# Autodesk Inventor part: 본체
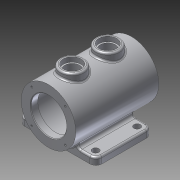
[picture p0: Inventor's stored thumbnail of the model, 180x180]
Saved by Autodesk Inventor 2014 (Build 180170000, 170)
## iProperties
Created: 2014-12
Part Number: 본체
Material: 알루미늄 6061
Document SubType Name: Modeling
Designer: Owner
Density: 2.71 g/cm^3
Appearance: 알루미늄 - 평지
Mass: 1293.91 g
Surface Area: 1040.15 cm^2
Volume: 477.456 cm^3
Author: Owner
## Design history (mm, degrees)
sketch "스케치1"
  geometry: C1 r 46 at (0, 0); 1 further point
  constraints: 1 centre point, 1 coincident
  dimensions: "d0" = 92 diameter of C1
extrude "돌출1" new body sketch "스케치1" stored distance "d1" = 140; taper "d2" = 0 deg
sketch "스케치2"
  geometry: C1 r 46 at (0, 0) reference; C2 r 30 at (0, 0)
  constraints: 1 centre point, 1 coincident
  dimensions: "d3" = 60 diameter of C2
extrude "돌출2" cut sketch "스케치2" stored distance "d4" = 0; taper "d5" = 0 deg
node "작업 평면1"
sketch "스케치3" dims "d28" = 40
  geometry: C1 r 37.5 at (0, 0); 1 further point
  constraints: 1 centre point, 1 coincident
  dimensions: "d7" = 75 diameter of C1
extrude "돌출3" cut sketch "스케치3" distance "d8" = 116; taper "d9" = 0 deg
node "작업 평면2"
sketch "스케치5"
  geometry: L1 (65, 40)-(-65, 40); L2 (-65, 40)-(-65, -55); L3 (-65, -55)-(65, -55); L4 (65, -55)-(65, 40); L5 (-46, -70)-(46, -70) reference; L6 (46, 70)-(-46, 70) reference; 2 further points
  constraints: 8 end point, 2 parallel, 1 horizontal, 1 midpoint, 1 perpendicular, 1 vertical alignment
  dimensions: "d13" = 130 distance of L3.end L2.end; "d14" = 95 distance of L2.end L1.end; "d15" = 15 distance between parallel lines of L5 L3
extrude "돌출4" join sketch "스케치5" distance "d16" = 12; taper "d17" = 0 deg
node "작업 평면3"
sketch "스케치7"
  geometry: L1 (-130, 6)-(-90.923, 6) reference; L2 (-130, -6)-(-130, 6) reference; L3 (-130, -6)-(0, -6) reference; L4 (0, -6)-(0, 6) reference; L5 (-39.077, 6)-(0, 6) reference; L6 (-39.077, 6)-(0, 6) reference; L7 (-130, 6)-(-90.923, 6) reference; C1 r 30 at (-65, 44) reference; C2 r 46 at (-65, 44) reference; A1 r 46 centre (-65, 44) between (-90.923, 6) and (-39.077, 6) reference; A2 r 5 centre (-26.116, 11) between (-29.928, 14.235) and (-26.116, 6); A3 r 5 centre (-103.884, 11) between (-103.884, 6) and (-100.072, 14.235); A4 r 46 centre (-65, 44) between (-39.077, 6) and (-90.923, 6) reference; 1 further point
  constraints: 6 point on circle, 4 tangent, 2 centre point, 2 point on line
  dimensions: "d18" = 10 diameter of A2; "d19" = 10 diameter of A3
extrude "돌출5" join sketch "스케치7" distance "d20" = 95; taper "d21" = 0 deg
node "작업 평면5"
sketch "스케치9"
  geometry: L1 (46, 70)-(-46, 70) reference; C1 r 20 at (0, 30); C2 r 20 at (0, -30); 1 further point
  constraints: 2 centre point, 2 vertical alignment
  dimensions: "d27" = 40 diameter of C1; "d28" = 40 diameter of C2; "d29" = 40 distance from line of C1.centre L1; "d30" = 60 distance of C2.centre C1.centre
extrude "돌출6" join sketch "스케치9" stored distance "d31" = 95; taper "d32" = 0 deg
sketch "스케치10"
  geometry: C1 r 20 at (0, 0) reference; 1 further point
sketch "스케치11"
  geometry: C1 r 20 at (0, 0) reference; 1 further point
hole "구멍1" sketch "스케치10" diameter "d33" = 25; stored, may be unused: countersink angle "d37" = 90 deg, drill point angle "d39" = 118 deg; dims "d34" = 6, "d35" = 30, "d36" = 8, "d38" = 8
hole "구멍2" sketch "스케치11" diameter "d40" = 25; stored, may be unused: countersink angle "d44" = 90 deg, drill point angle "d46" = 118 deg; dims "d41" = 6, "d42" = 30, "d43" = 8, "d45" = 8
sketch "스케치12"
  geometry: L1 (-38.884, 40)-(-65, 40) reference; L2 (-65, 40)-(-65, -55) reference; L3 (-65, -55)-(-38.884, -55) reference; C1 r 5.5 at (-52, 27.5); C2 r 5.5 at (-52, -42.5); 2 further points
  constraints: 2 centre point, 1 other
  dimensions: "d47" = 11 diameter of C1; "d48" = 11 diameter of C2; "d49" = 12.5 distance from line of C1.centre L1; "d50" = 12.5 distance from line of C2.centre L3; "d51" = 13 distance from line of C2.centre L2; "d52" = 13 distance from line of C1.centre L2
extrude "돌출7" cut sketch "스케치12" stored distance "d53" = 95; taper "d54" = 0 deg
sketch "스케치13"
  geometry: L1 (-65, 40)-(-65, -55) reference; C1 r 5.5 at (-52, 27.5) reference; 2 further points
  constraints: 1 other
  dimensions: "d55" = 8 distance from line of point (-57, -7.5) L1; "d56" = 35 vertical distance of point (-57, -7.5) C1.centre
feature "엠보싱1" sketch "스케치13" dims "d57" = 1, "d58" = 0
sketch "스케치14"
  geometry: L1 (0, 0)-(28.284, 28.284); L2 (0, 0)-(40, 0); L3 (0, 0)-(-28.284, 28.284); L4 (0, 0)-(-28.284, -28.284); L5 (0, 0)-(28.284, -28.284); C1 r 30 at (0, 0) reference; C2 r 46 at (0, 0) reference
  constraints: 10 end point, 1 equal length, 1 horizontal, 13 other
  dimensions: "d59" = 40 distance of L1.start L1.end; "d60" = 45 deg angle of L2 L1; "d63" = 360 deg dimension on C1.centre L1.end (derived)
hole "구멍3" sketch "스케치14" at (28.284, 28.284), (-28.284, 28.284), (-28.284, -28.284), (28.284, -28.284) diameter "d65" = 3.242; stored, may be unused: countersink angle "d69" = 90 deg, drill point angle "d71" = 118 deg; dims "d66" = 8, "d67" = 30, "d68" = 8, "d70" = 10
fillet "모깎기1" dims "d72" = 10
fillet "모깎기2" dims "d73" = 3
fillet "모깎기3" dims "d74" = 3
fillet "모깎기4" dims "d75" = 3
chamfer "모따기1" distance "d76" = 1; stored, may be unused: second distance "d77" = 2, angle "d78" = 45 deg
node "솔리드1"
mirror "대칭1"
mirror "대칭2"
node "투영된 루프1"
node "투영된 루프2"
node "투영된 루프3"
other parameters: "d6" = 58, "d26" = 56
